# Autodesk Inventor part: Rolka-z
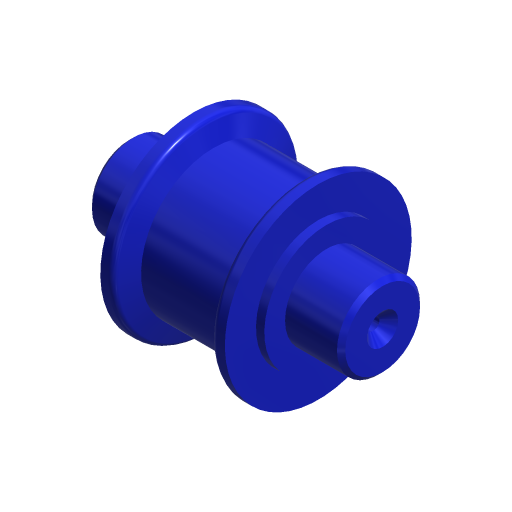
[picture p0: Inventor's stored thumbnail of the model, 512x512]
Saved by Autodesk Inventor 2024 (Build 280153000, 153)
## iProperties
Company: ATC
Shininess: 20.0
Length Units: 11269
Angle Units: 11279
Time Units: 11290
Mass Units: 11283
Length Display Precision: 3
Angle Display Precision: 2
Compacted: True
Created: 2023-03
Part Number: Rolka-z
Document SubType Name: Modeling
Designer: Andrzej Jaskulski
Material: Kurs-AJ
Density: 1 g/cm^3
Appearance: Niebieska — farba ścienna — lśniąca
Checked By: A.J.
Engr Approved By: Andrzej Jaskulski
Mfg Approved By: Andrzej Jaskulski
Authority: A.J.
Density: 0.0
Volumn: 0.0
Area: 0.0
PropertySet Name: Model Information
Control State: 0
Master: False
Checked Out: False
Title: A.J.: Kurs R2024-MEP
Author: Andrzej Jaskulski
Revision Number: 1/24
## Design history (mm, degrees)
node "Revolution1" dims "d7" = 90 deg
  sketch "Sketch1"
    geometry: L1 (32, 22.5)-(29, 22.5); L2 (29, 22.5)-(27.18, 17.5); L3 (27.18, 17.5)-(6.82, 17.5); L4 (6.82, 17.5)-(5, 22.5); L5 (5, 22.5)-(2, 22.5); L6 (32, 22.5)-(32, 15); L7 (32, 15)-(34, 15); L8 (34, 15)-(34, 0); L9 (2, 22.5)-(2, 15); L10 (2, 15)-(0, 15); L11 (0, 15)-(0, 0); L12 (0, 0)-(34, 0)
    constraints: 24 end point, 4 equal length, 4 parallel, 3 perpendicular, 1 horizontal, 1 other
    dimensions: "d2" = 3 distance of L1.start L1.end; "d4" = 110 deg angle of L3 L2; "d5" = 30 distance of L1.start L5.end (derived); "d12" = 17.5 distance between parallel lines of L3 L12; "d13" = 22.5 distance between parallel lines of L12 L1; "d14" = 15 distance of L7.end L8.end; "d15" = 2 distance of L6.end L7.end; "d39" = 110 deg angle of L4 L3 (= d4)
node "Fillet1" dims "d8" = 1.5
node "Extrusion1" dims "d16" = 0, "d17" = 13.5
node "Hole1" dims "d19" = 120 deg, "d20" = 90 deg, "d21" = 2, "d22" = 7.5, "d23" = 6.5, "d24" = 3
node "Chamfer2" dims "d25" = 1, "d26" = 1, "d41" = 45 deg
node "Extrusion2" dims "d27" = 0, "d28" = 13.5
node "Hole2" dims "d30" = 120 deg, "d31" = 90 deg, "d32" = 2, "d33" = 7.5, "d34" = 6.5, "d35" = 3
node "Chamfer3" dims "d36" = 1, "d37" = 1, "d42" = 45 deg
node "Bryła1"
node "Korpusy bryłowe"
node "Korpusy powierzchniowe"
sketch "Sketch2"
  geometry: C1 r 12.5 at (0, 0); C2 r 10 at (0, 0)
  constraints: 2 centre point, 1 coincident
  dimensions: "d18" = 20 diameter of C2
sketch "Sketch3"
  geometry: C1 r 10 at (0, 0) reference; 1 further point
  constraints: 1 coincident
sketch "Sketch4"
  geometry: C1 r 12.5 at (0, 0); C2 r 10 at (0, 0)
  constraints: 2 centre point, 1 coincident
  dimensions: "d29" = 20 diameter of C2
sketch "Sketch5"
  geometry: C1 r 10 at (0, 0) reference; 1 further point
  constraints: 1 coincident
